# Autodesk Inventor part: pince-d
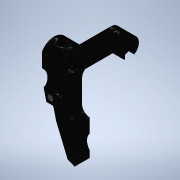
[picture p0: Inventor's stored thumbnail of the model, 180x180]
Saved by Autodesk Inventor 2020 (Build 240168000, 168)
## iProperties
Created: 2023-10
Part Number: pince-d
Material: Générique
Document SubType Name: Modeling
Designer: bruno
Density: 1 g/cm^3
Appearance: Noir
Author: bruno
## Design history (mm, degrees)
sketch "Esquisse1"
  geometry: L1 (-5.917, 4)-(-43.5, 4); L2 (-43.5, 4)-(-43.5, -4); L3 (-43.5, -4)-(-5.917, -4); L4 (-5.917, -4)-(-5.917, 4); C1 r 5 at (0, 0); C2 r 7.5 at (0, 0); 3 further points
  constraints: 8 end point, 2 centre point, 2 coincident, 2 parallel, 1 horizontal, 1 perpendicular
  dimensions: "d0" = 10 diameter of C1; "d1" = 15 diameter of C2; "d2" = 4 distance from line of L3 point (0, 0); "d3" = 4 distance from line of L1 point (0, 0); "d4" = 43.5 distance from line of L2 point (0, 0)
extrude "Extrusion1" new body sketch "Esquisse1" distance "d5" = 15; taper "d6" = 0 deg
sketch "Esquisse2"
  geometry: L1 (15, 37.156)-(15, 0) reference; L2 (0, 0)-(15, 0) reference; L3 (0, 37.156)-(0, 0) reference; L4 (23.715, 19)-(11, 19); L5 (11, 19)-(11, 53.427); L6 (11, 53.427)-(23.715, 53.427); L7 (23.715, 53.427)-(23.715, 19); L8 (15, 0)-(15, 37.156) reference; L9 (15, 0)-(11.265, 1.431); L10 (0, 0)-(0, 37.156) reference; L11 (0, 37.156)-(5.093, 16.193); L12 (5.093, 16.193)-(11.265, 1.431); C1 r 6.035 at (19.697, 7.524); 1 further point
  constraints: 14 end point, 2 parallel, 1 centre point, 1 horizontal, 1 perpendicular
  dimensions: "d7" = 4 distance between parallel lines of L5 L1; "d8" = 19 distance from line of L1.end L4; "d11" = 16 distance of L11.end L9.end; "d12" = 4 distance of L1.end L9.end
extrude "Extrusion2" cut sketch "Esquisse2" stored distance "d9" = 29; taper "d10" = 0 deg
fillet "Congé1" dims "d13" = 4
fillet "Congé2" dims "d14" = 4
sketch "Esquisse3"
  geometry: L1 (-22.111, 12.558)-(-6.5, 12.558); L2 (-6.5, 12.558)-(-6.5, -11.726); L3 (-6.5, -11.726)-(-22.111, -11.726); L4 (-22.111, -11.726)-(-22.111, 12.558); 1 further point
  constraints: 8 end point, 2 parallel, 1 horizontal, 1 perpendicular
  dimensions: "d15" = 6.5 distance from line of L2 point (0, 0)
extrude "Extrusion3" cut sketch "Esquisse3" distance "d16" = 20; taper "d17" = 0 deg
sketch "Esquisse4"
  geometry: L1 (-5.713, 5.5)-(12.395, 5.5); L2 (-3, 8.5)-(-3, 2.5); L3 (0, 0)-(0, 12.239) reference; L4 (-3, 8.5)-(0.406, 8.5); L5 (0.406, 8.5)-(0.406, 2.5); L6 (0.406, 2.5)-(-3, 2.5); L7 (-3, 2.5)-(-3, 8.5); 4 further points
  constraints: 12 end point, 2 horizontal, 2 parallel, 2 perpendicular
  dimensions: "d18" = 15 distance from line of L1 point (4, 20.5); "d19" = 3 distance between parallel lines of L3 L2; "d20" = 3 distance from line of L1 L2.start; "d30" = 3 distance between parallel lines of L1 L6
extrude "Extrusion4" join sketch "Esquisse4" stored distance "d22" = 20; taper "d23" = 0 deg
fillet "Congé3" dims "d24" = 4
sketch "Esquisse5"
  geometry: L1 (-8.168, 0)-(-9.626, 6) reference; L2 (0, 0)-(-8.168, 0) reference; L3 (0, 6)-(0, 0) reference; L4 (0, 6)-(-9.626, 6) reference; L5 (0, 3)-(-8.897, 3); L6 (-5.907, -9.307)-(-10.534, 9.739) reference; C1 r 1.5 at (-6.021, 3); 1 further point
  constraints: 2 end point, 2 point on line, 1 centre point, 1 horizontal, 1 midpoint
  dimensions: "d25" = 3 diameter of C1
extrude "Extrusion5" cut sketch "Esquisse5" distance "d26" = 10; taper "d27" = 0 deg
feature "Filetage1" dims "d28" = 10, "d29" = 0
sketch "Esquisse6"
  geometry: L1 (0.593, 25.5)-(18.5, 25.5); L2 (18.5, 25.5)-(18.5, 15.5); L3 (18.5, 15.5)-(0.593, 15.5); L4 (-10.5, 24.242)-(-10.5, 16.758) reference; L5 (0.593, 23.852)-(2.525, 19.91); L6 (2.525, 19.91)-(0.593, 16.758); L7 (0.593, 15.5)-(0.593, 16.758); L8 (0.593, 23.852)-(0.593, 25.5); 3 further points
  constraints: 14 end point, 3 parallel, 1 horizontal, 1 midpoint, 1 perpendicular, 3 other
  dimensions: "d31" = 10 distance between parallel lines of L3 L1; "d32" = 5 distance from line of L1 point (-4, 20.5); "d33" = 29 distance from line of point (18.5, 20.5) L4
extrude "Extrusion6" join sketch "Esquisse6" distance "d34" = 3; taper "d35" = 0 deg
sketch "Esquisse7"
  geometry: L1 (-10.5, 24.242)-(-10.5, 16.758) reference; L2 (-11, 8.5)-(-11, 2.5) reference; L3 (0, 0)-(-8.243, 0) reference; L4 (0, 12.239)-(0, 0) reference; L5 (1.59, 15.5)-(18.5, 15.5) reference; L6 (18.5, 25.5)-(1.59, 25.5) reference; C1 r 5 at (-4, 20.5) reference; A1 r 7.5 centre (-4, 20.5) between (1.59, 25.5) and (-10.5, 24.242) reference; A2 r 7.5 centre (-4, 20.5) between (-10.5, 16.758) and (-9.287, 15.181) reference; A3 r 4 centre (-12.107, 12.344) between (-11, 8.5) and (-9.287, 15.181) reference; A4 r 4 centre (-12, -1.373) between (-8.243, 0) and (-11, 2.5) reference; A5 r 4 centre (4, 12.239) between (1.217, 15.112) and (0, 12.239) reference; A6 r 7.5 centre (-4, 20.5) between (1.217, 15.112) and (1.59, 15.5) reference; A7 r 5 centre (18.5, 20.5) between (18.5, 15.5) and (18.5, 25.5) reference; A8 r 5 centre (18.5, 20.5) between (18.5, 15.5) and (18.5, 25.5) reference; 3 further points
  constraints: 1 coincident, 3 other
extrude "Extrusion7" join sketch "Esquisse7" distance "d36" = 7; taper "d37" = 0 deg
sketch "Esquisse8"
  geometry: L1 (-2.5, 5.527)-(2.5, 5.527); L2 (2.5, 5.527)-(2.5, -6.119); L3 (2.5, -6.119)-(-2.5, -6.119); L4 (-2.5, -6.119)-(-2.5, 5.527); C1 r 5 at (0, 0) reference; 5 further points
  constraints: 8 end point, 2 parallel, 1 horizontal, 1 perpendicular
  dimensions: "d38" = 2.5 distance from line of L2 C1.centre; "d39" = 2.5 distance from line of L4 C1.centre
extrude "Extrusion8" cut sketch "Esquisse8" distance "d40" = 3; taper "d41" = 0 deg
sketch "Esquisse9"
  geometry: C1 r 1.75 at (0, 0); 1 further point
  constraints: 1 centre point
  dimensions: "d42" = 3.5 diameter of C1
extrude "Extrusion9" cut sketch "Esquisse9" distance "d43" = 10; taper "d44" = 0 deg
node "Solide1"
node "Boucle projetée1"
node "Boucle projetée2"
node "Boucle projetée3"
